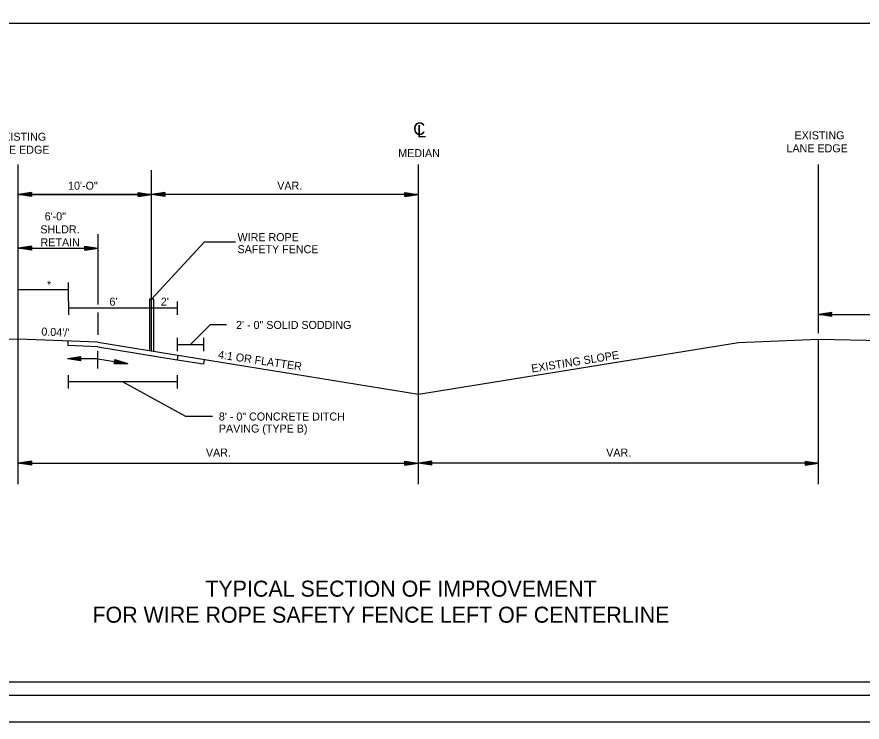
# Model space of a CAD drawing. Extents: x 1373889 to 1374222, y 382002 to 382215.
# Drawn here: x 1374000.3 to 1374127, y 382001.7 to 382107.3 of the extents above; entities that cross this region are included whole.
import ezdxf

# ---------------------------------------------------------------- set-up
doc = ezdxf.new("R2010")
doc.units = 0
for name, color, linetype in [('Default', 7, 'Continuous'), ('R_Border', 7, 'Continuous'), ('R_Draft', 7, 'Continuous'), ('R_No Plot', 7, 'Continuous')]:
    doc.layers.add(name, color=color, linetype=linetype)

msp = doc.modelspace()

# ---------------------------------------------------------------- linework, layer by layer
at = {"layer": 'Default'}
for q in [(1374009.84, 382056.1), (1374014.9, 382055.69)]:
    msp.add_line((1374012.39, 382056.1), q, dxfattribs=at)
at = {"layer": 'R_Border'}
msp.add_line((1374217.09, 382005.66), (1373900.91, 382005.66), dxfattribs=at)
at = {"layer": 'R_Draft'}
for p, q in [((1374000.44, 382037.34), (1374000.44, 382085.23)), ((1374060.44, 382037.34), (1374060.44, 382085.23)), ((1374120.44, 382059.96), (1374120.44, 382085.23)), ((1374020.44, 382057.27), (1374020.44, 382084.36)), ((1374002.44, 382081.02), (1374000.44, 382080.72)), ((1374002.44, 382080.97), (1374000.77, 382080.72)), ((1374002.44, 382080.92), (1374001.11, 382080.72)), ((1374002.44, 382080.87), (1374001.45, 382080.72)), ((1374002.44, 382080.82), (1374001.79, 382080.72)), ((1374002.44, 382080.77), (1374002.12, 382080.72)), ((1374002.44, 382081.02), (1374002.44, 382080.42)), ((1374018.44, 382081.02), (1374020.44, 382080.72)), ((1374018.44, 382080.42), (1374018.44, 382081.02)), ((1374018.44, 382080.97), (1374020.1, 382080.72)), ((1374018.44, 382080.92), (1374019.76, 382080.72)), ((1374018.44, 382080.87), (1374019.42, 382080.72)), ((1374018.44, 382080.82), (1374019.09, 382080.72)), ((1374018.44, 382080.77), (1374018.75, 382080.72)), ((1374022.44, 382081.02), (1374020.44, 382080.72)), ((1374022.44, 382080.97), (1374020.77, 382080.72)), ((1374022.44, 382080.92), (1374021.11, 382080.72)), ((1374022.44, 382080.87), (1374021.45, 382080.72)), ((1374022.44, 382080.82), (1374021.79, 382080.72)), ((1374022.44, 382080.77), (1374022.12, 382080.72)), ((1374022.44, 382081.02), (1374022.44, 382080.42)), ((1374058.44, 382081.02), (1374060.44, 382080.72)), ((1374058.44, 382080.42), (1374058.44, 382081.02)), ((1374058.44, 382080.97), (1374060.1, 382080.72)), ((1374058.44, 382080.92), (1374059.76, 382080.72)), ((1374058.44, 382080.87), (1374059.42, 382080.72)), ((1374058.44, 382080.82), (1374059.09, 382080.72)), ((1374058.44, 382080.77), (1374058.75, 382080.72)), ((1374000.44, 382080.72), (1374020.44, 382080.72)), ((1374002.44, 382080.42), (1374000.44, 382080.72)), ((1374060.44, 382080.72), (1374000.44, 382080.72)), ((1374002.44, 382080.47), (1374000.77, 382080.72)), ((1374002.44, 382080.52), (1374001.11, 382080.72)), ((1374002.44, 382080.57), (1374001.45, 382080.72)), ((1374002.44, 382080.62), (1374001.79, 382080.72)), ((1374002.44, 382080.67), (1374002.12, 382080.72)), ((1374018.44, 382080.42), (1374020.44, 382080.72)), ((1374018.44, 382080.62), (1374019.09, 382080.72)), ((1374018.44, 382080.52), (1374019.76, 382080.72)), ((1374018.44, 382080.47), (1374020.1, 382080.72)), ((1374018.44, 382080.57), (1374019.42, 382080.72)), ((1374018.44, 382080.67), (1374018.75, 382080.72)), ((1374022.44, 382080.42), (1374020.44, 382080.72)), ((1374022.44, 382080.47), (1374020.77, 382080.72)), ((1374022.44, 382080.52), (1374021.11, 382080.72)), ((1374022.44, 382080.57), (1374021.45, 382080.72)), ((1374022.44, 382080.62), (1374021.79, 382080.72)), ((1374022.44, 382080.67), (1374022.12, 382080.72)), ((1374058.44, 382080.42), (1374060.44, 382080.72)), ((1374058.44, 382080.62), (1374059.09, 382080.72)), ((1374058.44, 382080.52), (1374059.76, 382080.72)), ((1374058.44, 382080.47), (1374060.1, 382080.72)), ((1374058.44, 382080.57), (1374059.42, 382080.72)), ((1374058.44, 382080.67), (1374058.75, 382080.72)), ((1374012.44, 382064.24), (1374012.44, 382074.76)), ((1374020.44, 382065.05), (1374028.37, 382073.6)), ((1374028.37, 382073.6), (1374033.01, 382073.6)), ((1374002.44, 382072.98), (1374000.44, 382072.68)), ((1374000.44, 382072.68), (1374012.44, 382072.68)), ((1374002.44, 382072.38), (1374000.44, 382072.68)), ((1374002.44, 382072.93), (1374000.77, 382072.68)), ((1374002.44, 382072.43), (1374000.77, 382072.68)), ((1374002.44, 382072.87), (1374001.11, 382072.68)), ((1374002.44, 382072.48), (1374001.11, 382072.68)), ((1374002.44, 382072.82), (1374001.45, 382072.68)), ((1374002.44, 382072.53), (1374001.45, 382072.68)), ((1374002.44, 382072.77), (1374001.79, 382072.68)), ((1374002.44, 382072.58), (1374001.79, 382072.68)), ((1374002.44, 382072.72), (1374002.12, 382072.68)), ((1374002.44, 382072.63), (1374002.12, 382072.68)), ((1374002.44, 382072.98), (1374002.44, 382072.38)), ((1374010.44, 382072.98), (1374012.44, 382072.68)), ((1374010.44, 382072.38), (1374010.44, 382072.98)), ((1374010.44, 382072.93), (1374012.1, 382072.68)), ((1374010.44, 382072.87), (1374011.76, 382072.68)), ((1374010.44, 382072.82), (1374011.42, 382072.68)), ((1374010.44, 382072.77), (1374011.09, 382072.68)), ((1374010.44, 382072.72), (1374010.75, 382072.68)), ((1374010.44, 382072.38), (1374012.44, 382072.68)), ((1374010.44, 382072.58), (1374011.09, 382072.68)), ((1374010.44, 382072.48), (1374011.76, 382072.68)), ((1374010.44, 382072.43), (1374012.1, 382072.68)), ((1374010.44, 382072.53), (1374011.42, 382072.68)), ((1374010.44, 382072.63), (1374010.75, 382072.68)), ((1374007.99, 382064.68), (1374007.99, 382067.53)), ((1374000.44, 382066.47), (1374007.99, 382066.47)), ((1374007.99, 382064.68), (1374007.99, 382062.68)), ((1374020.72, 382065.05), (1374020.13, 382065.05)), ((1374020.13, 382065.05), (1374020.13, 382057.28)), ((1374020.72, 382065.05), (1374020.72, 382057.26)), ((1374024.31, 382064.68), (1374024.31, 382062.68)), ((1374024.31, 382063.68), (1374007.99, 382063.68)), ((1374012.44, 382059.67), (1374012.44, 382063.02)), ((1374122.43, 382063.03), (1374120.43, 382062.73)), ((1374122.43, 382062.43), (1374122.43, 382063.03)), ((1374120.43, 382062.73), (1374144.41, 382062.73)), ((1374122.43, 382062.43), (1374120.43, 382062.73)), ((1374122.43, 382062.98), (1374120.76, 382062.73)), ((1374122.43, 382062.48), (1374120.76, 382062.73)), ((1374122.43, 382062.93), (1374121.1, 382062.73)), ((1374122.43, 382062.53), (1374121.1, 382062.73)), ((1374122.43, 382062.88), (1374121.44, 382062.73)), ((1374122.43, 382062.58), (1374121.44, 382062.73)), ((1374122.43, 382062.83), (1374121.78, 382062.73)), ((1374122.43, 382062.63), (1374121.78, 382062.73)), ((1374122.43, 382062.77), (1374122.11, 382062.73)), ((1374122.43, 382062.68), (1374122.11, 382062.73)), ((1374026.28, 382058.23), (1374029.29, 382061.24)), ((1374029.29, 382061.24), (1374031.68, 382061.24)), ((1374024.31, 382059.23), (1374024.31, 382057.23)), ((1374028.26, 382059.23), (1374028.26, 382057.23)), ((1374000.44, 382059.06), (1373976.12, 382058.58)), ((1374012.38, 382058.58), (1374000.44, 382059.06)), ((1374007.96, 382058.07), (1374007.96, 382058.76)), ((1374012.39, 382057.89), (1374007.96, 382058.07)), ((1374012.38, 382058.58), (1374060.44, 382050.78)), ((1374024.31, 382058.23), (1374028.26, 382058.23)), ((1374060.44, 382050.78), (1374108.44, 382058.56)), ((1374108.44, 382058.56), (1374120.44, 382059.04)), ((1374120.44, 382059.04), (1374144.41, 382058.57)), ((1374120.44, 382045.95), (1374120.44, 382058.89)), ((1374012.38, 382054.63), (1374012.39, 382057.23)), ((1374012.39, 382057.89), (1374024.31, 382055.96)), ((1374120.44, 382037.34), (1374120.44, 382057.17)), ((1374009.84, 382056.4), (1374007.84, 382056.1)), ((1374009.84, 382055.8), (1374007.84, 382056.1)), ((1374009.84, 382056.35), (1374008.17, 382056.1)), ((1374009.84, 382055.85), (1374008.17, 382056.1)), ((1374009.84, 382056.3), (1374008.51, 382056.1)), ((1374009.84, 382055.9), (1374008.51, 382056.1)), ((1374009.84, 382056.25), (1374008.85, 382056.1)), ((1374009.84, 382055.95), (1374008.85, 382056.1)), ((1374009.84, 382056.2), (1374009.19, 382056.1)), ((1374009.84, 382056), (1374009.19, 382056.1)), ((1374009.84, 382056.15), (1374009.52, 382056.1)), ((1374009.84, 382056.05), (1374009.52, 382056.1)), ((1374009.84, 382055.8), (1374009.84, 382056.4)), ((1374014.85, 382055.39), (1374014.95, 382055.99)), ((1374014.85, 382055.39), (1374016.88, 382055.37)), ((1374014.86, 382055.44), (1374016.55, 382055.42)), ((1374014.87, 382055.49), (1374016.21, 382055.48)), ((1374014.88, 382055.54), (1374015.88, 382055.53)), ((1374014.89, 382055.59), (1374015.54, 382055.59)), ((1374014.9, 382055.64), (1374015.21, 382055.64)), ((1374014.91, 382055.74), (1374015.21, 382055.64)), ((1374014.92, 382055.79), (1374015.54, 382055.59)), ((1374014.93, 382055.89), (1374016.21, 382055.48)), ((1374014.93, 382055.84), (1374015.88, 382055.53)), ((1374014.94, 382055.94), (1374016.55, 382055.42)), ((1374014.95, 382055.99), (1374016.88, 382055.37)), ((1374024.39, 382056.63), (1374024.31, 382055.96)), ((1374024.31, 382055.96), (1374028.26, 382055.32)), ((1374028.34, 382055.99), (1374028.26, 382055.32)), ((1374007.96, 382053.65), (1374007.96, 382051.65)), ((1374024.31, 382053.65), (1374024.31, 382051.65)), ((1374024.31, 382052.65), (1374007.96, 382052.65)), ((1374016.13, 382052.65), (1374025.52, 382047.49)), ((1374025.52, 382047.49), (1374029.61, 382047.49)), ((1374002.44, 382040.77), (1374000.44, 382040.47)), ((1374002.44, 382040.17), (1374000.44, 382040.47)), ((1374000.44, 382040.47), (1374060.44, 382040.47)), ((1374002.44, 382040.72), (1374000.77, 382040.47)), ((1374002.44, 382040.22), (1374000.77, 382040.47)), ((1374002.44, 382040.67), (1374001.11, 382040.47)), ((1374002.44, 382040.27), (1374001.11, 382040.47)), ((1374002.44, 382040.62), (1374001.45, 382040.47)), ((1374002.44, 382040.32), (1374001.45, 382040.47)), ((1374002.44, 382040.57), (1374001.79, 382040.47)), ((1374002.44, 382040.37), (1374001.79, 382040.47)), ((1374002.44, 382040.52), (1374002.12, 382040.47)), ((1374002.44, 382040.42), (1374002.12, 382040.47)), ((1374002.44, 382040.77), (1374002.44, 382040.17)), ((1374058.44, 382040.77), (1374060.44, 382040.47)), ((1374058.44, 382040.17), (1374058.44, 382040.77)), ((1374058.44, 382040.72), (1374060.1, 382040.47)), ((1374058.44, 382040.67), (1374059.76, 382040.47)), ((1374058.44, 382040.62), (1374059.42, 382040.47)), ((1374058.44, 382040.57), (1374059.09, 382040.47)), ((1374058.44, 382040.52), (1374058.75, 382040.47)), ((1374058.44, 382040.17), (1374060.44, 382040.47)), ((1374058.44, 382040.37), (1374059.09, 382040.47)), ((1374058.44, 382040.27), (1374059.76, 382040.47)), ((1374058.44, 382040.22), (1374060.1, 382040.47)), ((1374058.44, 382040.32), (1374059.42, 382040.47)), ((1374058.44, 382040.42), (1374058.75, 382040.47)), ((1374062.44, 382040.77), (1374060.44, 382040.47)), ((1374120.44, 382040.47), (1374060.44, 382040.47)), ((1374062.44, 382040.17), (1374060.44, 382040.47)), ((1374062.44, 382040.72), (1374060.77, 382040.47)), ((1374062.44, 382040.22), (1374060.77, 382040.47)), ((1374062.44, 382040.67), (1374061.11, 382040.47)), ((1374062.44, 382040.27), (1374061.11, 382040.47)), ((1374062.44, 382040.62), (1374061.45, 382040.47)), ((1374062.44, 382040.32), (1374061.45, 382040.47)), ((1374062.44, 382040.57), (1374061.79, 382040.47)), ((1374062.44, 382040.37), (1374061.79, 382040.47)), ((1374062.44, 382040.52), (1374062.12, 382040.47)), ((1374062.44, 382040.42), (1374062.12, 382040.47)), ((1374062.44, 382040.17), (1374062.44, 382040.77)), ((1374118.44, 382040.77), (1374120.44, 382040.47)), ((1374118.44, 382040.77), (1374118.44, 382040.17)), ((1374118.44, 382040.72), (1374120.1, 382040.47)), ((1374118.44, 382040.67), (1374119.76, 382040.47)), ((1374118.44, 382040.62), (1374119.42, 382040.47)), ((1374118.44, 382040.57), (1374119.09, 382040.47)), ((1374118.44, 382040.52), (1374118.75, 382040.47)), ((1374118.44, 382040.17), (1374120.44, 382040.47)), ((1374118.44, 382040.37), (1374119.09, 382040.47)), ((1374118.44, 382040.27), (1374119.76, 382040.47)), ((1374118.44, 382040.22), (1374120.1, 382040.47)), ((1374118.44, 382040.32), (1374119.42, 382040.47)), ((1374118.44, 382040.42), (1374118.75, 382040.47))]:
    msp.add_line(p, q, dxfattribs=at)
at = {"layer": 'R_No Plot'}
for points in [[(1373888.51, 382215.01), (1374221.85, 382215.01), (1374221.85, 382001.67), (1373888.51, 382001.67)], [(1373902.91, 382209.12), (1374152.45, 382209.12), (1374152.45, 382199.24), (1374169.99, 382199.24), (1374194.09, 382199.24), (1374194.09, 382176.9), (1374215.09, 382176.9), (1374215.09, 382007.66), (1373902.91, 382007.66)], [(1373902.91, 382106.39), (1374215.09, 382106.39), (1374215.09, 382007.66), (1373902.91, 382007.66)]]:
    msp.add_lwpolyline(points, close=True, dxfattribs=at)

# ---------------------------------------------------------------- texts
at = {"layer": 'R_Draft'}
for s, height, p in [('C', 1.88, (1374059.67, 382089.63)), ('L', 1.88, (1374060.24, 382089.26)), ('EXISTING', 1.2, (1373997.16, 382088.77)), ('EXISTING', 1.2, (1374116.83, 382088.98)), ('LANE EDGE', 1.2, (1373995.96, 382086.82)), ('MEDIAN', 1.2, (1374057.43, 382086.31)), ('LANE EDGE', 1.2, (1374115.63, 382087.03)), ('10\'-O"', 1.2, (1374007.94, 382081.43)), ('VAR.', 1.2, (1374039.29, 382081.43)), ('6\'-0"', 1.2, (1374004.43, 382076.84)), ('SHLDR.', 1.2, (1374003.78, 382074.89)), ('WIRE ROPE', 1.2, (1374033.34, 382073.72)), ('RETAIN', 1.2, (1374003.81, 382072.94)), ('SAFETY FENCE', 1.2, (1374033.34, 382071.92)), ('*', 1.2, (1374004.78, 382066.6)), ("6'", 1.2, (1374014.14, 382064.06)), ("2'", 1.2, (1374021.84, 382064.06)), ('2\' - 0" SOLID SODDING', 1.2, (1374033.12, 382060.57)), ('8\' - 0" CONCRETE DITCH ', 1.2, (1374030.54, 382046.85)), ('PAVING (TYPE B)', 1.2, (1374030.54, 382045.05)), ('VAR.', 1.2, (1374028.6, 382041.45)), ('VAR.', 1.2, (1374088.6, 382041.45)), ('TYPICAL SECTION OF IMPROVEMENT', 2.4, (1374028.51, 382020.46)), ('FOR WIRE ROPE SAFETY FENCE LEFT OF CENTERLINE', 2.4, (1374011.59, 382016.56))]:
    msp.add_text(s, height=height, dxfattribs=at).set_placement(p)
for s, rotation, p in [("0.04'/'", 357.626, (1374003.91, 382059.59)), ('4:1 OR FLATTER', 351.6564, (1374030.36, 382056.17)), ('EXISTING SLOPE', 9.0617, (1374077.47, 382054.03))]:
    msp.add_text(s, height=1.2, rotation=rotation, dxfattribs=at).set_placement(p)

doc.saveas('drawing.dxf')
